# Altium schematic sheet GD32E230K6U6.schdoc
size 127 x 101 mm
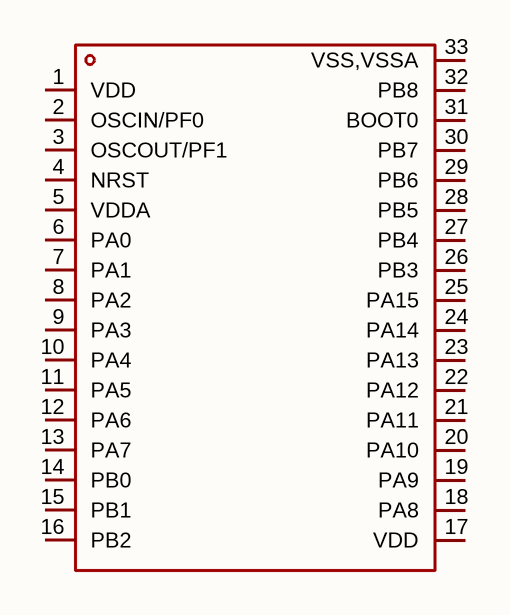
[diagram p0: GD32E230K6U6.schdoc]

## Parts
U?  gd32e230k6u6  [QFN-32_L5.0-W5.0-P0.50-BL-EP3.4]  (value not drawn)

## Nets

Not connected (* = marked no-connect by the designer): U? 1(VDD) 2(OSCIN/PF0) 3(OSCOUT/PF1) 4(NRST) 5(VDDA) 6(PA0) 7(PA1) 8(PA2) 9(PA3) 10(PA4) 11(PA5) 12(PA6) 13(PA7) 14(PB0) 15(PB1) 16(PB2) 17(VDD) 18(PA8) 19(PA9) 20(PA10) 21(PA11) 22(PA12) 23(PA13) 24(PA14) 25(PA15) 26(PB3) 27(PB4) 28(PB5) 29(PB6) 30(PB7) 31(BOOT0) 32(PB8) 33(VSS,VSSA)

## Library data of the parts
U? = gd32e230k6u6: CPU内核:ARM Cortex-M系列;CPU最大主频:72MHz;; Manufacturer: GigaDevice(兆易创新); AddInBom: yes; ModelId: 9cd7b3b2e5534eca85488abae33e32e3; ModelName: QFN-32_L5.0-W5.0-H0.9-P0.50; ModelTransform: 197.6374,197.6374,0,90,0,0,-0.789,-0.395,0; CPU Maximum Speed: 72MHz; Program Storage Size: 64KB; Program Memory Type: FLASH; Number of I/O: 39; ADC (Bit): 10bit；8bit；6bit；12bit; Voltage - Supply: 1.8V~3.6V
